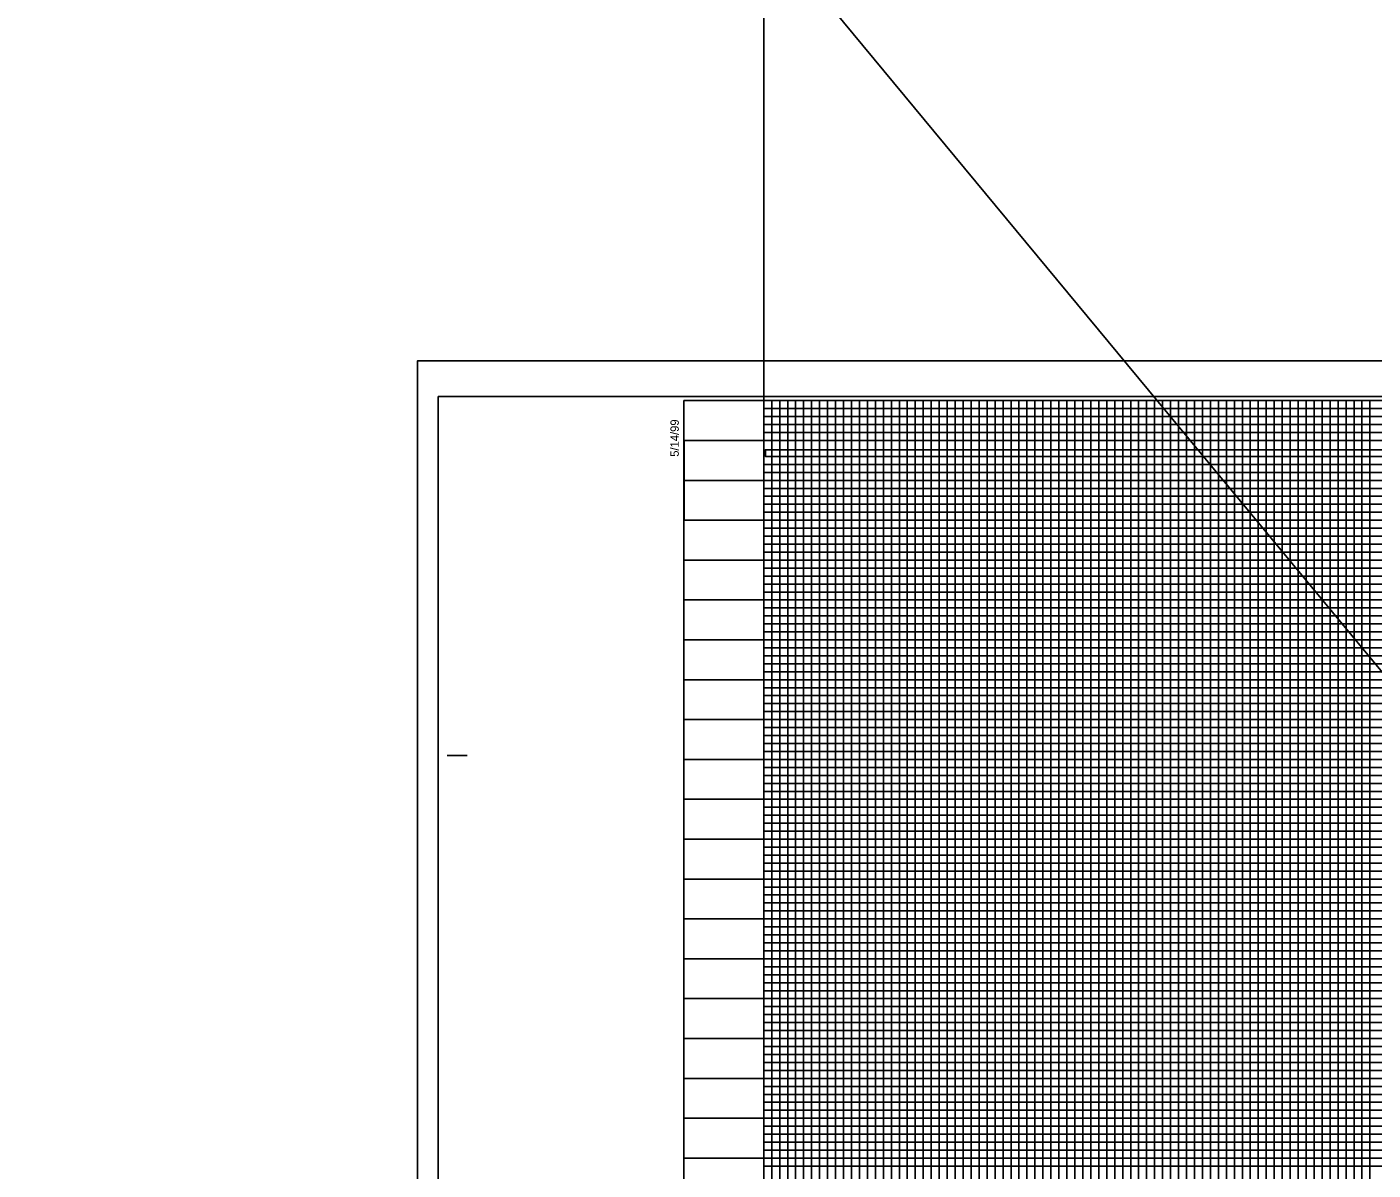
# Model space of a CAD drawing. Extents: x 2345490 to 2436403, y 465165 to 573888.
# Drawn here: x 2410433 to 2411277, y 523748 to 524465 of the extents above; entities that cross this region are included whole.
import ezdxf

# ---------------------------------------------------------------- set-up
doc = ezdxf.new("R2010")
doc.units = 0
for name, color, linetype in [('Old_Level_18', 7, 'Continuous'), ('Old_Level_41', 7, 'Continuous'), ('Old_Level_42', 7, 'Continuous'), ('Old_Level_43', 7, 'Continuous'), ('Old_Level_50', 7, 'Continuous'), ('Old_Level_51', 7, 'Continuous'), ('Old_Level_62', 7, 'Continuous'), ('Old_Level_63', 7, 'Continuous')]:
    doc.layers.add(name, color=color, linetype=linetype)

msp = doc.modelspace()

# ---------------------------------------------------------------- linework, layer by layer
at = {"layer": 'Old_Level_18'}
msp.add_lwpolyline([(2412345.325, 524230.9495), (2410845.325, 524230.9495), (2410845.325, 523180.9495), (2412345.325, 523180.9495)], close=True, dxfattribs=at)
at = {"layer": 'Old_Level_41'}
msp.add_line((2410696.825, 524008.4495), (2410709.325, 524008.4495), dxfattribs=at)
for points in [[(2410845.325, 524230.9495), (2410895.325, 524230.9495), (2410895.325, 523205.9495), (2410945.325, 523205.9495), (2410945.325, 524230.9495), (2410995.325, 524230.9495), (2410995.325, 523205.9495), (2411045.325, 523205.9495), (2411045.325, 524230.9495), (2411095.325, 524230.9495), (2411095.325, 523205.9495), (2411145.325, 523205.9495), (2411145.325, 524230.9495), (2411195.325, 524230.9495), (2411195.325, 523205.9495), (2411245.325, 523205.9495), (2411245.325, 524230.9495), (2411295.325, 524230.9495)], [(2410920.325, 523205.9495), (2410920.325, 524230.9495), (2410970.325, 524230.9495), (2410970.325, 523205.9495), (2411020.325, 523205.9495), (2411020.325, 524230.9495), (2411070.325, 524230.9495), (2411070.325, 523205.9495), (2411120.325, 523205.9495), (2411120.325, 524230.9495), (2411170.325, 524230.9495), (2411170.325, 523205.9495), (2411220.325, 523205.9495), (2411220.325, 524230.9495), (2411270.325, 524230.9495), (2411270.325, 523205.9495), (2411320.325, 523205.9495)], [(2410845.325, 524180.9495), (2412145.275, 524180.9495)], [(2412145.275, 524130.9495), (2410845.325, 524130.9495), (2410845.325, 524080.8995), (2412345.325, 524080.8995)], [(2412345.325, 524055.9495), (2410845.325, 524055.9495), (2410845.325, 524105.9495), (2412145.275, 524105.9495)], [(2412345.325, 524030.9495), (2410845.325, 524030.9495), (2410845.325, 523980.9495), (2412345.325, 523980.9495)], [(2412345.325, 523955.9495), (2410845.325, 523955.9495), (2410845.325, 524005.9495), (2412345.325, 524005.9495)], [(2412345.325, 523930.9495), (2410845.325, 523930.9495), (2410845.325, 523880.9495), (2412345.325, 523880.9495)], [(2412345.325, 523830.9495), (2410845.325, 523830.9495), (2410845.325, 523780.9495), (2412345.325, 523780.9495)]]:
    msp.add_lwpolyline(points, dxfattribs=at)
at = {"layer": 'Old_Level_42'}
for points in [[(2412145.275, 524155.9495), (2410845.425, 524155.9495), (2410845.425, 524205.8995), (2412145.275, 524205.8995)], [(2412345.325, 523855.9495), (2410845.325, 523855.9495), (2410845.325, 523905.9495), (2412345.325, 523905.9495)], [(2412345.325, 523755.9495), (2410845.325, 523755.9495), (2410845.325, 523805.9495), (2412345.325, 523805.9495)]]:
    msp.add_lwpolyline(points, dxfattribs=at)
at = {"layer": 'Old_Level_43'}
for p, q in [((2412295.325, 524050.9495), (2410895.325, 524050.9495)), ((2410895.325, 524050.9495), (2410895.325, 524045.9495)), ((2410895.325, 524045.9495), (2412295.325, 524045.9495)), ((2412295.325, 524025.9495), (2410895.325, 524025.9495))]:
    msp.add_line(p, q, dxfattribs=at)
for points in [[(2410900.325, 524230.9495), (2410905.325, 524230.9495), (2410910.325, 524230.9495), (2410915.325, 524230.9495), (2410925.325, 524230.9495), (2410892.275, 524230.9495), (2410897.275, 524230.9495), (2410855.325, 524230.9495), (2410860.325, 524230.9495), (2410865.325, 524230.9495), (2410875.325, 524230.9495), (2410880.325, 524230.9495), (2410885.325, 524230.9495), (2410890.325, 524230.9495), (2410900.325, 524230.9495), (2410900.325, 523205.9495)], [(2412145.275, 524225.9495), (2410895.325, 524225.9495), (2410895.325, 524220.9495), (2412145.275, 524220.9495)], [(2410905.325, 523205.9495), (2410905.325, 524230.9495), (2410910.325, 524230.9495), (2410910.325, 523205.9495)], [(2410915.325, 523205.9495), (2410915.325, 524230.9495), (2410925.325, 524230.9495), (2410925.325, 523205.9495)], [(2410930.325, 523205.9495), (2410930.325, 524230.9495), (2410935.325, 524230.9495), (2410935.325, 523205.9495)], [(2410940.325, 523205.9495), (2410940.325, 524230.9495), (2410950.325, 524230.9495), (2410950.325, 523205.9495)], [(2410955.325, 523205.9495), (2410955.325, 524230.9495), (2410960.325, 524230.9495), (2410960.325, 523205.9495)], [(2410965.325, 523205.9495), (2410965.325, 524230.9495), (2410975.325, 524230.9495), (2410975.325, 523205.9495)], [(2410980.325, 523205.9495), (2410980.325, 524230.9495), (2410985.325, 524230.9495), (2410985.325, 523205.9495)], [(2410990.325, 523205.9495), (2410990.325, 524230.9495), (2411000.325, 524230.9495), (2411000.325, 523205.9495)], [(2411005.325, 523205.9495), (2411005.325, 524230.9495), (2411010.325, 524230.9495), (2411010.325, 523205.9495)], [(2411015.325, 523205.9495), (2411015.325, 524230.9495), (2411025.325, 524230.9495), (2411025.325, 523205.9495)], [(2411030.325, 523205.9495), (2411030.325, 524230.9495), (2411035.325, 524230.9495), (2411035.325, 523205.9495)], [(2411040.325, 523205.9495), (2411040.325, 524230.9495), (2411050.325, 524230.9495), (2411050.325, 523205.9495)], [(2411055.325, 523205.9495), (2411055.325, 524230.9495), (2411060.325, 524230.9495), (2411060.325, 523205.9495)], [(2411065.325, 523205.9495), (2411065.325, 524230.9495), (2411075.325, 524230.9495), (2411075.325, 523205.9495)], [(2411080.325, 523205.9495), (2411080.325, 524230.9495), (2411085.325, 524230.9495), (2411085.325, 523205.9495)], [(2411090.325, 523205.9495), (2411090.325, 524230.9495), (2411100.325, 524230.9495), (2411100.325, 523205.9495)], [(2411105.325, 523205.9495), (2411105.325, 524230.9495), (2411105.325, 524230.9495), (2411110.325, 524230.9495), (2411110.325, 523205.9495)], [(2411115.325, 523205.9495), (2411115.325, 524230.9495), (2411125.325, 524230.9495), (2411125.325, 523205.9495)], [(2411130.325, 523205.9495), (2411130.325, 524230.9495), (2411135.325, 524230.9495), (2411135.325, 523205.9495)], [(2411140.325, 523205.9495), (2411140.325, 524230.9495), (2411150.325, 524230.9495), (2411150.325, 523205.9495)], [(2411155.325, 523205.9495), (2411155.325, 524230.9495), (2411160.325, 524230.9495), (2411160.325, 523205.9495)], [(2411165.325, 523205.9495), (2411165.325, 524230.9495), (2411175.325, 524230.9495), (2411175.325, 523205.9495)], [(2411180.325, 523205.9495), (2411180.325, 524230.9495), (2411185.325, 524230.9495), (2411185.325, 523205.9495)], [(2411190.325, 523205.9495), (2411190.325, 524230.9495), (2411200.325, 524230.9495), (2411200.325, 523205.9495)], [(2411205.325, 523205.9495), (2411205.325, 524230.9495), (2411210.325, 524230.9495), (2411210.325, 523205.9495)], [(2411215.325, 523205.9495), (2411215.325, 524230.9495), (2411225.325, 524230.9495), (2411225.325, 523205.9495)], [(2411230.325, 524230.9495), (2411230.325, 523205.9495), (2411235.325, 523205.9495), (2411235.325, 524230.9495)], [(2411230.325, 524230.3495), (2411230.325, 523205.9495), (2411235.325, 523205.9495), (2411235.325, 524230.3495)], [(2411240.325, 523205.9495), (2411240.325, 524230.9495), (2411250.325, 524230.9495), (2411250.325, 523205.9495)], [(2411255.325, 523205.9495), (2411255.325, 524230.9495), (2411260.325, 524230.9495), (2411260.325, 523205.9495)], [(2411265.325, 523205.9495), (2411265.325, 524230.9495), (2411275.325, 524230.9495), (2411275.325, 523205.9495)], [(2412145.275, 524215.9495), (2410895.325, 524215.9495), (2410895.325, 524210.9495), (2412145.275, 524210.9495)], [(2412145.275, 524200.1995), (2410896.325, 524200.1995), (2410896.325, 524195.9495), (2412145.275, 524195.9495)], [(2412145.275, 524190.9495), (2410895.325, 524190.9495), (2410895.325, 524185.9495), (2412145.275, 524185.9495)], [(2412145.275, 524175.9495), (2410895.325, 524175.9495), (2410895.325, 524170.9495), (2412145.275, 524170.9495)], [(2412145.275, 524165.9495), (2410895.325, 524165.9495), (2410895.325, 524160.9495), (2412145.275, 524160.9495)], [(2412145.275, 524150.9495), (2410895.325, 524150.9495), (2410895.325, 524145.9495), (2412145.275, 524145.9495)], [(2412145.275, 524140.9495), (2410895.325, 524140.9495), (2410895.325, 524135.9495), (2412145.275, 524135.9495)], [(2412145.275, 524125.9495), (2410895.325, 524125.9495), (2410895.325, 524120.9495), (2412145.275, 524120.9495)], [(2412145.275, 524115.9495), (2410895.325, 524115.9495), (2410895.325, 524110.9495), (2412145.275, 524110.9495)], [(2412145.275, 524100.9495), (2410895.325, 524100.9495), (2410895.325, 524095.9495), (2412145.275, 524095.9495)], [(2412295.325, 524090.9495), (2410895.325, 524090.9495), (2410895.325, 524090.9495), (2410895.325, 524070.9495), (2412295.325, 524070.9495)], [(2410895.325, 524085.9495), (2412295.325, 524085.9495)], [(2412295.325, 524075.9495), (2410895.325, 524075.9495)], [(2412295.325, 524065.9495), (2410895.325, 524065.9495), (2410895.325, 524060.9495), (2412295.325, 524060.9495)], [(2412295.325, 524040.9495), (2410895.325, 524040.9495), (2410895.325, 524035.9495), (2412295.325, 524035.9495)], [(2412295.325, 524020.9495), (2410895.325, 524020.9495), (2410895.325, 524015.9495), (2412295.325, 524015.9495)], [(2412295.325, 524010.9495), (2410895.325, 524010.9495)], [(2410895.325, 524000.9495), (2412295.325, 524000.9495)], [(2412295.325, 523995.9495), (2410895.325, 523995.9495), (2410895.325, 523990.9495), (2412295.325, 523990.9495)], [(2412295.325, 523985.9495), (2410895.325, 523985.9495), (2410895.325, 523975.9495), (2412295.325, 523975.9495)], [(2412295.325, 523970.9495), (2410895.325, 523970.9495), (2410895.325, 523965.9495), (2412295.325, 523965.9495)], [(2412295.325, 523960.9495), (2410895.325, 523960.9495), (2410895.325, 523950.9495), (2412295.325, 523950.9495)], [(2412295.325, 523945.9495), (2410895.325, 523945.9495), (2410895.325, 523940.9495), (2412295.325, 523940.9495)], [(2412295.325, 523935.9495), (2410895.325, 523935.9495), (2410895.325, 523925.9495), (2412295.325, 523925.9495)], [(2412295.325, 523920.9495), (2410895.325, 523920.9495), (2410895.325, 523915.9495), (2412295.325, 523915.9495)], [(2412295.325, 523910.9495), (2410895.325, 523910.9495), (2410895.325, 523900.9495), (2412295.325, 523900.9495)], [(2412295.325, 523895.9495), (2410895.325, 523895.9495), (2410895.325, 523890.9495), (2412295.325, 523890.9495)], [(2412295.325, 523885.9495), (2410895.325, 523885.9495), (2410895.325, 523875.9495), (2412295.325, 523875.9495)], [(2412295.325, 523870.9495), (2410895.325, 523870.9495), (2410895.325, 523865.9495), (2412295.325, 523865.9495)], [(2412295.325, 523860.9495), (2410895.325, 523860.9495), (2410895.325, 523850.9495), (2412295.325, 523850.9495)], [(2412295.325, 523845.9495), (2410895.325, 523845.9495), (2410895.325, 523840.9495), (2412295.325, 523840.9495)], [(2412295.325, 523835.9495), (2410895.325, 523835.9495), (2410895.325, 523825.9495), (2412295.325, 523825.9495)], [(2412295.325, 523820.9495), (2410895.325, 523820.9495), (2410895.325, 523815.9495), (2412295.325, 523815.9495)], [(2412295.325, 523810.9495), (2410895.325, 523810.9495), (2410895.325, 523800.9495), (2412295.325, 523800.9495)], [(2412295.325, 523795.9495), (2410895.325, 523795.9495), (2410895.325, 523790.9495), (2412295.325, 523790.9495)], [(2412295.325, 523785.9495), (2410895.325, 523785.9495), (2410895.325, 523775.9495), (2412295.325, 523775.9495)], [(2412295.325, 523770.9495), (2410895.325, 523770.9495), (2410895.325, 523765.9495), (2412295.325, 523765.9495)], [(2412295.325, 523760.9495), (2410895.325, 523760.9495), (2410895.325, 523750.9495), (2412295.325, 523750.9495)]]:
    msp.add_lwpolyline(points, dxfattribs=at)
at = {"layer": 'Old_Level_50'}
msp.add_lwpolyline([(2412357.825, 524233.4995), (2410691.325, 524233.4995), (2410691.325, 523178.3995), (2412357.825, 523178.3995)], close=True, dxfattribs=at)
at = {"layer": 'Old_Level_51'}
msp.add_lwpolyline([(2412362.325, 524255.9495), (2410678.325, 524255.9495), (2410678.325, 523155.9495), (2412362.325, 523155.9495)], close=True, dxfattribs=at)
at = {"layer": 'Old_Level_62'}
msp.add_line((2411634.29674, 523636.10645), (2410433.44219, 525086.84544), dxfattribs=at)
at = {"layer": 'Old_Level_63'}
msp.add_line((2410895.325, 523205.9495), (2410895.325, 525705.9495), dxfattribs=at)

# ---------------------------------------------------------------- texts
at = {"layer": 'Old_Level_41'}
msp.add_text('5/14/99', height=5.25, rotation=90, dxfattribs=at).set_placement((2410842.075, 524195.7495))

doc.saveas('drawing.dxf')
